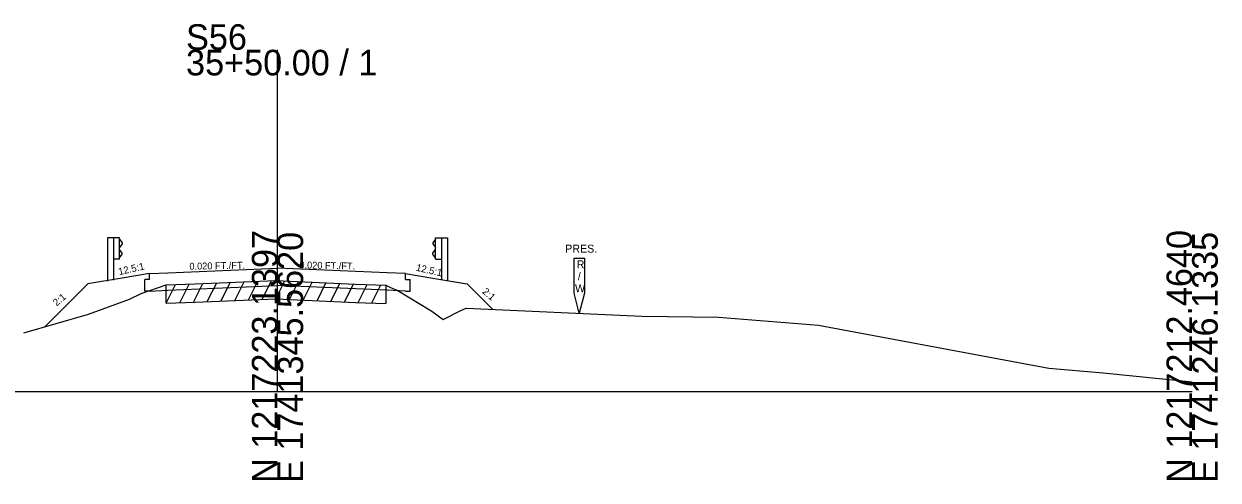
# Model space of a CAD drawing. Extents: x -26 to 1203, y -10 to 19541.
# Drawn here: x 72.3 to 202.8, y 10490.3 to 10540.3 of the extents above; entities that cross this region are included whole.
import ezdxf

# ---------------------------------------------------------------- set-up
doc = ezdxf.new("R2010")
doc.units = 0
for name, color, linetype in [('RD_GPK_XS_Cell', 7, 'Continuous'), ('RD_XS_Base', 7, 'Continuous'), ('RD_XS_EarthShd', 7, 'Continuous'), ('RD_XS_ExGround', 7, 'Continuous'), ('RD_XS_ExPaveRet', 7, 'Continuous'), ('RD_XS_ExRW', 7, 'Continuous'), ('RD_XS_GR', 7, 'Continuous'), ('RD_XS_Pave', 7, 'Continuous'), ('RD_XS_TX_Elev_EX', 7, 'Continuous'), ('RD_XS_TX_Slope', 7, 'Continuous')]:
    doc.layers.add(name, color=color, linetype=linetype)

msp = doc.modelspace()

# ---------------------------------------------------------------- linework, layer by layer
at = {"layer": 'RD_GPK_XS_Cell'}
for p, q in [((100, 10500), (100, 10537.41)), ((0, 10500), (100, 10500)), ((100, 10500), (200, 10500))]:
    msp.add_line(p, q, dxfattribs=at)
at = {"layer": 'RD_XS_Base'}
for p, q in [((86, 10512.28), (85.5, 10512.26)), ((85.5, 10510.99), (85.5, 10512.26)), ((86, 10512.28), (86, 10512.92)), ((114, 10512.28), (114, 10512.92)), ((114, 10512.28), (114.5, 10512.26)), ((114.5, 10510.99), (114.5, 10512.26)), ((86, 10511.01), (85.5, 10510.99)), ((86, 10511.01), (88, 10511.1)), ((88, 10511.1), (100, 10511.6)), ((112, 10511.1), (100, 10511.6)), ((114, 10511.01), (112, 10511.1)), ((114, 10511.01), (114.5, 10510.99))]:
    msp.add_line(p, q, dxfattribs=at)
at = {"layer": 'RD_XS_EarthShd'}
for p, q in [((83, 10512.42), (79.25, 10511.79)), ((83, 10512.42), (79.5, 10511.84)), ((86, 10512.92), (83, 10512.42)), ((114, 10512.92), (117, 10512.42)), ((117, 10512.42), (120.5, 10511.84)), ((117, 10512.42), (120.75, 10511.79)), ((74.56, 10507.1), (79.25, 10511.79)), ((123.55, 10508.99), (120.75, 10511.79))]:
    msp.add_line(p, q, dxfattribs=at)
at = {"layer": 'RD_XS_ExGround'}
msp.add_lwpolyline([(72.25, 10506.44), (79.33, 10508.48), (83.82, 10510.13), (85.11, 10510.73), (87.82, 10511.67), (91.01, 10511.8), (99.81, 10512.16), (108.54, 10511.75), (111.85, 10511.66), (112.34, 10511.38), (113.1, 10511.12), (116.86, 10508.8), (118.13, 10507.88), (120.06, 10508.88), (120.62, 10509.12), (139.84, 10508.26), (148.2, 10508.15), (159.15, 10507.28), (184.34, 10502.57), (190.26, 10502.05), (200, 10501.08)], dxfattribs=at)
at = {"layer": 'RD_XS_ExPaveRet'}
for p, q in [((95.32, 10509.98), (96.35, 10512.02)), ((96.82, 10510.04), (97.85, 10512.08)), ((98.32, 10510.1), (99.35, 10512.14)), ((99.82, 10510.16), (100.8, 10512.12)), ((101.32, 10510.09), (102.3, 10512.05)), ((87.82, 10509.67), (88.84, 10511.71)), ((87.82, 10509.67), (87.82, 10511.67)), ((89.32, 10509.73), (90.34, 10511.77)), ((90.82, 10509.79), (91.85, 10511.83)), ((92.32, 10509.85), (93.35, 10511.89)), ((93.82, 10509.91), (94.85, 10511.96)), ((102.82, 10510.02), (103.8, 10511.98)), ((104.32, 10509.95), (105.3, 10511.91)), ((105.82, 10509.88), (106.8, 10511.84)), ((107.32, 10509.81), (108.3, 10511.76)), ((108.82, 10509.75), (109.81, 10511.72)), ((110.32, 10509.7), (111.31, 10511.68)), ((111.85, 10511.66), (111.85, 10509.66)), ((87.82, 10509.67), (91.01, 10509.8)), ((91.01, 10509.8), (99.81, 10510.16)), ((99.81, 10510.16), (108.54, 10509.75)), ((108.54, 10509.75), (111.85, 10509.66))]:
    msp.add_line(p, q, dxfattribs=at)
at = {"layer": 'RD_XS_ExRW'}
msp.add_lwpolyline([(132.45, 10514.59), (133.55, 10514.59), (133.55, 10510.76), (133, 10508.57), (132.45, 10510.76)], close=True, dxfattribs=at)
at = {"layer": 'RD_XS_GR'}
for p, q in [((81.4, 10516.84), (81.4, 10512.07)), ((82.06, 10516.84), (81.4, 10516.84)), ((82.06, 10516.84), (82.06, 10512.18)), ((82.73, 10516.84), (82.06, 10516.84)), ((82.73, 10514.5), (82.73, 10516.84)), ((82.73, 10516.69), (83, 10516.29)), ((83, 10516.19), (82.73, 10515.79)), ((83, 10516.29), (83, 10516.19)), ((117.27, 10516.69), (117, 10516.29)), ((117, 10516.29), (117, 10516.19)), ((117, 10516.19), (117.27, 10515.79)), ((117.27, 10514.5), (117.27, 10516.84)), ((117.27, 10516.84), (117.94, 10516.84)), ((117.94, 10516.84), (117.94, 10512.18)), ((117.94, 10516.84), (118.6, 10516.84)), ((118.6, 10516.84), (118.6, 10512.07)), ((83, 10515.15), (82.73, 10515.55)), ((82.73, 10514.65), (83, 10515.05)), ((83, 10515.05), (83, 10515.15)), ((117, 10515.15), (117.27, 10515.55)), ((117, 10515.05), (117, 10515.15)), ((117.27, 10514.65), (117, 10515.05)), ((82.73, 10514.5), (82.06, 10514.5)), ((117.27, 10514.5), (117.94, 10514.5))]:
    msp.add_line(p, q, dxfattribs=at)
at = {"layer": 'RD_XS_Pave'}
for p, q in [((88, 10513), (100, 10513.5)), ((112, 10513), (100, 10513.5)), ((86, 10512.92), (88, 10513)), ((114, 10512.92), (112, 10513))]:
    msp.add_line(p, q, dxfattribs=at)

# ---------------------------------------------------------------- texts
at = {"layer": 'RD_GPK_XS_Cell'}
for s, p in [('S56', (90, 10537.41)), ('35+50.00 / 1', (90, 10534.61))]:
    msp.add_text(s, height=2.8, dxfattribs=at).set_placement(p)
for s, p in [('N 1217223.1397', (100, 10490)), ('E 1741345.5620', (102.8, 10490)), ('N 1217212.4640', (200, 10490)), ('E 1741246.1335', (202.8, 10490))]:
    msp.add_text(s, height=2.8, rotation=90, dxfattribs=at).set_placement(p)
at = {"layer": 'RD_XS_ExRW'}
for s, p in [('PRES.', (131.45, 10515.21)), ('R', (132.71, 10513.49)), ('/', (132.83, 10512.18)), ('W', (132.53, 10510.87))]:
    msp.add_text(s, height=0.875, dxfattribs=at).set_placement(p)
at = {"layer": 'RD_XS_TX_Elev_EX'}
msp.add_text('850.08', height=0.1, rotation=90, dxfattribs=at).set_placement((100.1, 10512.15))
at = {"layer": 'RD_XS_TX_Slope'}
for s, height, rotation, p in [('12.5:1', 0.778, 12.7511, (82.69, 10512.74)), ('0.020 FT./FT.', 0.7518, 1.1916, (90.38, 10513.34)), ('0.020 FT./FT.', 0.7518, 358.8084, (102.39, 10513.49)), ('12.5:1', 0.778, 347.2489, (115.09, 10513.24)), ('2:1', 0.778, 40.6589, (75.86, 10509.31)), ('2:1', 0.778, 319.3411, (122.32, 10510.84))]:
    msp.add_text(s, height=height, rotation=rotation, dxfattribs=at).set_placement(p)

doc.saveas('drawing.dxf')
